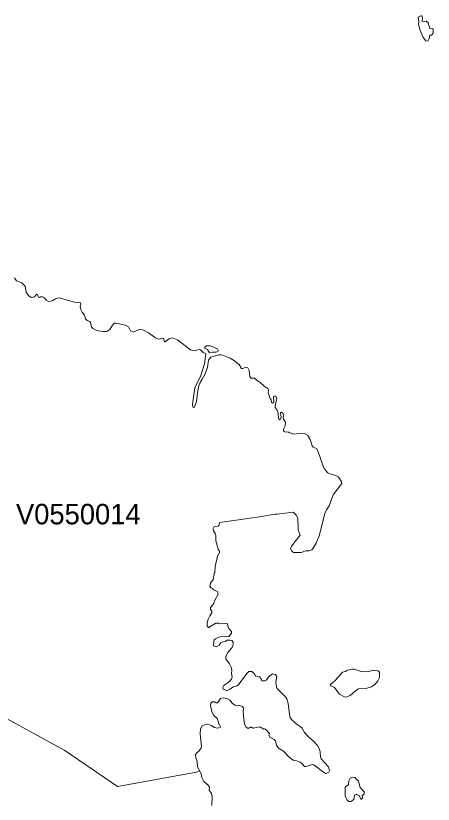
# Model space of a CAD drawing. Extents: x 369010 to 735936, y 6377141 to 6616555.
# Drawn here: x 448245 to 450287, y 6488735 to 6492592 of the extents above; entities that cross this region are included whole.
import ezdxf
from ezdxf.enums import TextEntityAlignment as Align

# ---------------------------------------------------------------- set-up
doc = ezdxf.new("R2010")
doc.units = 0
doc.header["$LTSCALE"] = 40
doc.layers.add('3', color=7, linetype='Continuous', lineweight=13)
doc.layers.add('4', color=7, linetype='Continuous')

msp = doc.modelspace()

# ---------------------------------------------------------------- linework, layer by layer
at = {"layer": '3'}
for points in [[(450233.78, 6492583.83), (450230.63, 6492591.28), (450226.49, 6492591.61), (450213.25, 6492584.83), (450217.06, 6492562.65), (450215.57, 6492549.24), (450222.85, 6492520.28), (450238.24, 6492485.69), (450251.15, 6492468.64), (450261.08, 6492466.66), (450267.87, 6492479.9), (450270.02, 6492495.95), (450278.79, 6492496.94), (450286.74, 6492505.88), (450287.07, 6492526.4), (450281.61, 6492529.55), (450273.83, 6492527.4), (450271.01, 6492529.55), (450262.41, 6492556.86), (450252.81, 6492564.97), (450233.44, 6492563.64)], [(449197.89, 6490976.79), (449177.69, 6490977.78), (449169.25, 6490970.17), (449170.58, 6490964.38), (449183.16, 6490958.91), (449192.76, 6490942.53), (449206.66, 6490946.5), (449225.53, 6490946.01), (449236.45, 6490953.45), (449231.81, 6490962.06)], [(449935.04, 6489385.3), (449901.11, 6489395.23), (449891.51, 6489395.23), (449868.01, 6489391.26), (449858.08, 6489384.97), (449843.35, 6489381.66), (449808.1, 6489340.95), (449784.6, 6489320.09), (449784.27, 6489314.3), (449802.31, 6489308.18), (449828.95, 6489273.59), (449856.59, 6489259.52), (449864.54, 6489260.18), (449880.59, 6489267.79), (449906.91, 6489290.63), (449922.3, 6489299.24), (449956.89, 6489300.56), (449985.85, 6489309.5), (450003.06, 6489323.07), (450016.3, 6489338.46), (450024.58, 6489355.68), (450024.25, 6489381), (450018.29, 6489387.12), (449994.13, 6489391.59), (449965.33, 6489383.32)], [(449893.33, 6488867.44), (449880.92, 6488861.98), (449874.8, 6488849.4), (449872.81, 6488830.86), (449859.41, 6488822.59), (449856.26, 6488816.8), (449856.59, 6488776.25), (449865.53, 6488755.73), (449873.47, 6488749.11), (449884.07, 6488748.77), (449898.3, 6488758.7), (449902.44, 6488779.23), (449907.9, 6488782.7), (449914.19, 6488783.03), (449924.45, 6488777.9), (449933.55, 6488760.52), (449936.37, 6488760.52), (449941.5, 6488765.16), (449940.01, 6488776.25), (449948.61, 6488786.84), (449948.61, 6488795.61), (449929.91, 6488817.95), (449921.64, 6488848.74), (449903.1, 6488866.12)]]:
    msp.add_lwpolyline(points, close=True, dxfattribs=at)
for points in [[(448308.47, 6491221.4), (448296.22, 6491237.95), (448290.59, 6491268.41), (448275.2, 6491285.95), (448249.22, 6491295.22), (448238.46, 6491309.29)], [(449480.24, 6490746.74), (449481.73, 6490762.79), (449478.58, 6490768.58), (449460.38, 6490780.17), (449438.2, 6490799.04), (449425.29, 6490807.48), (449412.21, 6490819.89), (449404.44, 6490818.4), (449394.5, 6490819.89), (449390.04, 6490827.67), (449386.89, 6490856.47), (449380.77, 6490869.38), (449377.46, 6490871.86), (449371.17, 6490872.19), (449355.45, 6490865.9), (449348.99, 6490867.06), (449338.07, 6490886.09), (449310.76, 6490906.62), (449293.55, 6490917.21), (449261.44, 6490930.28), (449249.19, 6490933.59), (449237.61, 6490933.59), (449199.54, 6490922.67), (449188.62, 6490906.62), (449182.16, 6490871.86), (449169.25, 6490837.27), (449157.17, 6490813.6), (449144.92, 6490794.24), (449140.13, 6490781.49), (449133.67, 6490749.39), (449128.54, 6490704.37), (449118.61, 6490677.23), (449115.13, 6490675.9), (449112.49, 6490677.56), (449110.33, 6490683.35), (449110, 6490691.63), (449120.93, 6490772.39), (449150.06, 6490831.48), (449168.1, 6490889.24), (449175.38, 6490937.4), (449161.64, 6490944.35), (449149.06, 6490956.93), (449138.8, 6490959.58), (449122.09, 6490953.12), (449109.34, 6490954.11), (449100.07, 6490956.93), (449036.85, 6491006.91), (449011.86, 6491016.68), (448993.82, 6491010.88), (448975.78, 6490997.31), (448971.97, 6490997.64), (448971.31, 6491004.76), (448967.84, 6491013.03), (448965.02, 6491014.36), (448944.67, 6491010.22), (448928.78, 6491017.17), (448894.52, 6491041.17), (448866.05, 6491055.57), (448849.5, 6491057.55), (448821.03, 6491043.49), (448806.63, 6491050.77), (448795.71, 6491070.96), (448780.32, 6491077.75), (448735.63, 6491088.84), (448726.53, 6491088.34), (448717.92, 6491078.9), (448704.85, 6491057.89), (448690.78, 6491047.62), (448673.57, 6491046.96), (448650.4, 6491050.44), (448633.19, 6491055.9), (448622.26, 6491062.69), (448615.97, 6491069.97), (448610.84, 6491091.81), (448606.71, 6491096.61), (448594.79, 6491100.42), (448586.51, 6491109.69), (448580.72, 6491127.23), (448569.14, 6491141.3), (448563.51, 6491154.21), (448560.2, 6491169.93), (448562.85, 6491179.7), (448561.52, 6491186.81), (448559.04, 6491189.63), (448532.06, 6491190.62), (448457.26, 6491212.47), (448439.88, 6491207), (448422.67, 6491196.74), (448405.45, 6491194.1), (448393.87, 6491200.88), (448386.25, 6491212.14), (448375.5, 6491217.6), (448366.39, 6491216.94), (448360.44, 6491213.79), (448356.13, 6491214.78), (448352, 6491227.2), (448346.86, 6491229.35), (448336.27, 6491216.94), (448320.55, 6491213.29), (448308.47, 6491221.4)], [(449197.89, 6489817.1), (449210.96, 6489834.31), (449215.43, 6489864.27), (449218.08, 6489869.07), (449220.06, 6489897.87), (449232.15, 6489949.17), (449241.58, 6489966.55), (449241.74, 6489972.35), (449234.79, 6489982.61), (449223.87, 6490024.31), (449224.2, 6490050.3), (449222.55, 6490056.09), (449212.62, 6490072.48), (449210.13, 6490084.23), (449215.76, 6490093.33), (449234.79, 6490095.81), (449238.77, 6490098.96), (449242.74, 6490112.53), (449437.54, 6490140.99), (449513.83, 6490154.07), (449525.75, 6490153.57), (449547.6, 6490157.38), (449602.71, 6490163.34), (449616.94, 6490148.94), (449624.56, 6490134.37), (449624.06, 6490119.64), (449626.71, 6490102.43), (449626.87, 6490076.94), (449635.81, 6490050.63), (449593.44, 6489997.34), (449588.14, 6489984.43), (449596.09, 6489973.67), (449603.7, 6489966.88), (449641.6, 6489965.89), (449664.28, 6489974.83), (449678.51, 6489974.83), (449692.58, 6489979.13), (449702.18, 6489990.88), (449714.76, 6490012.07), (449728.49, 6490047.48), (449756.13, 6490157.05), (449765.4, 6490175.42), (449778.81, 6490194.29), (449797.51, 6490248.57), (449840.04, 6490304.35), (449838.39, 6490312.29), (449822.99, 6490335.79), (449806.44, 6490344.23), (449786.91, 6490349.36), (449771.85, 6490356.65), (449756.79, 6490372.37), (449750.67, 6490384.28), (449723.36, 6490463.89), (449716.24, 6490474.48), (449700.36, 6490482.43), (449694.56, 6490487.89), (449685.13, 6490519.34), (449673.38, 6490539.2), (449662.46, 6490545.32), (449661.79, 6490547.31), (449632.83, 6490548.8), (449604.03, 6490544.66), (449592.45, 6490550.12), (449584.5, 6490552.11), (449580.86, 6490554.92), (449575.24, 6490556.24), (449564.64, 6490555.58), (449558.19, 6490557.9), (449554.55, 6490563.36), (449555.21, 6490569.15), (449562.33, 6490586.36), (449565.14, 6490604.07), (449554.38, 6490618.8), (449553.39, 6490628.07), (449555.54, 6490639.66), (449552.4, 6490646.11), (449544.12, 6490652.24), (449539.49, 6490649.92), (449542.47, 6490628.07), (449539.16, 6490617.81), (449536.67, 6490616.16), (449531.54, 6490618.8), (449528.56, 6490635.85), (449529.23, 6490648.59), (449523.76, 6490662.5), (449514.5, 6490675.9), (449513.5, 6490680.7), (449514.83, 6490692.29), (449522.61, 6490718.93), (449519.29, 6490728.53), (449516.48, 6490731.02), (449507.71, 6490730.52), (449506.22, 6490727.54), (449507.38, 6490703.54), (449501.09, 6490696.43), (449498.11, 6490697.75), (449495.63, 6490702.22), (449493.64, 6490713.14), (449489.84, 6490719.26), (449480.24, 6490746.74)], [(449721.21, 6489022.68), (449700.52, 6489045.52), (449676.52, 6489065.05), (449656.99, 6489086.24), (449645.08, 6489109.08), (449613.3, 6489131.75), (449592.12, 6489150.95), (449587.98, 6489158.73), (449583.51, 6489174.12), (449577.06, 6489228.07), (449570.6, 6489251.08), (449565.47, 6489258.86), (449523.43, 6489301.23), (449520.62, 6489308.84), (449517.97, 6489332.01), (449521.28, 6489360.48), (449519.29, 6489365.28), (449514.83, 6489369.91), (449500.76, 6489372.72), (449487.19, 6489363.79), (449480.9, 6489357.33), (449469.97, 6489341.94), (449462.86, 6489338.63), (449449.45, 6489338.63), (449445.15, 6489349.06), (449436.54, 6489358.99), (449419.83, 6489361.14), (449414.03, 6489368.26), (449413.21, 6489372.72), (449399.3, 6489383.98), (449385.9, 6489384.31), (449374.98, 6489374.71), (449337.74, 6489324.23), (449327.48, 6489314.3), (449310.76, 6489310.16), (449292.89, 6489297.59), (449280.64, 6489291.63), (449277.49, 6489291.63), (449259.78, 6489298.58), (449257.47, 6489303.05), (449258.79, 6489309.17), (449263.26, 6489315.29), (449290.24, 6489336.15), (449300.17, 6489346.41), (449303.48, 6489358.33), (449299.84, 6489375.04), (449301.16, 6489390.43), (449299.01, 6489405.82), (449290.9, 6489421.22), (449273.19, 6489445.88), (449272.03, 6489459.61), (449282.62, 6489477.98), (449300.17, 6489498.18), (449304.97, 6489505.79), (449309.27, 6489518.37), (449308.61, 6489527.64), (449301.16, 6489535.41), (449293.55, 6489537.9), (449279.31, 6489537.9), (449271.04, 6489533.43), (449255.98, 6489528.63), (449248.53, 6489524.16), (449239.92, 6489513.57), (449225.86, 6489505.46), (449212.62, 6489510.42), (449213.28, 6489533.76), (449215.43, 6489539.55), (449221.55, 6489545.01), (449236.95, 6489552.46), (449252.34, 6489555.94), (449275.51, 6489553.95), (449287.09, 6489555.28), (449300.83, 6489571.66), (449300.5, 6489579.6), (449287.09, 6489594.33), (449283.12, 6489605.92), (449281.13, 6489618.99), (449239.76, 6489618), (449235.46, 6489620.32), (449223.54, 6489620.32), (449190.11, 6489599.8), (449187.96, 6489599.8), (449180.84, 6489607.24), (449181.5, 6489623.3), (449186.96, 6489640.68), (449194.08, 6489656.4), (449203.68, 6489671.79), (449203.68, 6489680.07), (449196.89, 6489688.01), (449196.89, 6489696.12), (449202.69, 6489704.39), (449214.6, 6489716.64), (449216.42, 6489730.71), (449234.46, 6489762.16), (449231.48, 6489775.73), (449212.29, 6489784.33), (449206.82, 6489790.46), (449201.36, 6489792.94), (449194.91, 6489801.71), (449197.89, 6489817.1)], [(449204.67, 6488728.75), (449205, 6488771.78), (449202.69, 6488788.5), (449191.76, 6488804.55), (449193.09, 6488819.28), (449185.31, 6488830.2), (449164.79, 6488845.92), (449154.86, 6488866.78), (449152.04, 6488883.49), (449144.43, 6488898.22), (449128.71, 6488892.76), (448742.75, 6488821.76), (448485.89, 6488997.86), (448213.96, 6489146.65), (448119.96, 6489198.12), (447706.53, 6489407.81), (447531.1, 6489470.87), (447108.07, 6489321.75), (447036.9, 6489397.55), (446862.13, 6489376.7)], [(448213.96, 6489146.65), (448485.89, 6488997.86), (448742.75, 6488821.76), (449128.71, 6488892.76), (449144.43, 6488898.22), (449133.34, 6488919.41), (449132.68, 6488944.4), (449126.39, 6488962.27), (449124.73, 6488977), (449129.53, 6488985.78), (449141.45, 6488996.37), (449152.37, 6489010.44), (449153.2, 6489018.21), (449146.25, 6489079.78), (449149.06, 6489104.11), (449157.5, 6489118.68), (449167.76, 6489124.14), (449183.16, 6489127.28), (449200.7, 6489120.17), (449216.42, 6489110.9), (449231.81, 6489107.42), (449244.39, 6489110.23), (449246.05, 6489113.88), (449240.26, 6489127.61), (449237.94, 6489129.27), (449234.13, 6489146.15), (449230.32, 6489153.93), (449213.28, 6489169.32), (449205.17, 6489184.38), (449198.22, 6489215.16), (449198.88, 6489229.56), (449206.16, 6489236.68), (449218.74, 6489236.02), (449224.86, 6489230.89), (449231.48, 6489230.89), (449234.13, 6489232.87), (449246.05, 6489251.74), (449261.44, 6489255.38), (449277.99, 6489253.06), (449291.56, 6489244.13), (449302.82, 6489229.23), (449316.55, 6489220.63), (449331.94, 6489216.82), (449339.72, 6489217.48), (449353.79, 6489212.68), (449358.92, 6489204.9), (449357.27, 6489189.51), (449360.58, 6489150.95), (449364.71, 6489127.94), (449370.84, 6489113.54), (449378.78, 6489108.08), (449386.23, 6489107.75), (449393.84, 6489112.22), (449398.31, 6489112.22), (449406.09, 6489107.75), (449439.52, 6489113.54), (449458.72, 6489102.95), (449463.19, 6489104.11), (449474.77, 6489094.18), (449482.72, 6489083.26), (449486.03, 6489083.92), (449485.04, 6489071.51), (449488.18, 6489063.4), (449509.36, 6489052.47), (449515.16, 6489046.18), (449520.62, 6489024.67), (449529.89, 6489010.27), (449554.88, 6488995.38), (449581.86, 6488965.25), (449602.71, 6488951.19), (449618.1, 6488947.71), (449635.48, 6488940.26), (449644.75, 6488933.81), (449657.33, 6488920.4), (449664.94, 6488919.08), (449694.89, 6488929.67), (449702.51, 6488928.68), (449749.68, 6488891.77), (449760.27, 6488885.15), (449763.08, 6488885.15), (449775.99, 6488891.77), (449779.47, 6488898.22), (449774.34, 6488918.42), (449739.42, 6488956.98), (449736.27, 6488966.91), (449734.28, 6488989.91), (449731.14, 6489005.31), (449721.21, 6489022.68)]]:
    msp.add_lwpolyline(points, dxfattribs=at)

# ---------------------------------------------------------------- texts
at = {"layer": '4'}
msp.add_text('V0550014', height=100, dxfattribs=at).set_placement((448550.92, 6490104.26), align=Align.CENTER)

doc.saveas('drawing.dxf')
